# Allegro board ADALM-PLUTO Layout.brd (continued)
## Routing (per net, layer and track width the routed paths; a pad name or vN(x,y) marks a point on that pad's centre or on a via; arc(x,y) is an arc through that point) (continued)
IO_L04_34_RX_D7: length 49.7
  TOP w0.102: U5.J9 v2(27.54,30.48) ; v2(53.13,28.15) U4.J14
  L5_SIG w0.114: v2(27.54,30.48) 27.54,29.97 28.17,29.34 28.17,25.47 28.55,25.09 28.85,25.09 28.99,25.24 28.99,26.22 29.14,26.36 29.34,26.36 29.45,26.26 29.45,25.27 29.66,25.05 31,25.05 31.6,25.65 31.6,26.22 31.75,26.36 31.95,26.36 32.1,26.22 32.1,25.75 32.24,25.6 32.45,25.6 32.59,25.75 32.59,26.22 32.74,26.36 32.94,26.36 33.09,26.22 33.09,25.75 33.23,25.6 33.44,25.6 33.58,25.75 33.58,26.22 33.73,26.36 33.93,26.36 34.08,26.22 34.08,25.75 34.22,25.6 34.43,25.6 34.57,25.75 34.57,26.22 34.72,26.36 34.92,26.36 35.07,26.22 35.07,25.75 35.21,25.6 35.42,25.6 35.56,25.75 35.56,26.22 35.71,26.36 35.91,26.36 36.06,26.22 36.06,25.75 36.2,25.6 37.99,25.6 38.13,25.46 38.13,25.11 38.28,24.97 38.48,24.97 38.63,25.11 38.63,25.46 38.77,25.6 39.72,25.6 40.39,24.93 40.54,24.93 40.76,24.71 40.76,24.57 41.81,23.51 41.81,23.31 41.38,22.88 41.38,22.67 41.53,22.53 41.73,22.53 42.16,22.96 42.37,22.96 42.51,22.81 42.51,22.61 42.21,22.3 42.21,22.1 42.36,21.95 42.56,21.95 42.86,22.26 43.07,22.26 43.41,21.92 50.52,21.92 52.73,24.13 52.73,27.75 v2(53.13,28.15)
IO_L05_34_RX_D8: length 49
  TOP w0.102: U5.K7 v2(26.74,31.28) ; v2(53.13,27.35) U4.J15
  L5_SIG w0.114: v2(53.13,27.35) 53.13,23.89 50.77,21.54 41.88,21.54 41.75,21.67 40.98,21.67 40.87,21.79 40.87,22.43 40.74,22.55 40.74,22.78 41.26,23.3 41.26,23.51 41.11,23.65 40.91,23.65 40.44,23.18 40.24,23.18 40.09,23.33 40.09,23.53 40.36,23.8 40.36,23.98 40.2,24.14 39.99,24.14 39.74,23.88 39.54,23.88 39.39,24.03 39.39,24.12 39.85,24.58 39.85,24.84 39.6,25.09 39.39,25.09 38.56,24.25 38.25,24.25 37.75,24.76 37.75,25.07 37.6,25.22 37.4,25.22 37.31,25.13 37.31,24.79 37.06,24.53 36.5,24.53 36.35,24.68 36.35,24.98 36.21,25.13 36.02,25.13 35.91,25.02 35.91,24.71 35.81,24.61 35.61,24.61 35.53,24.69 35.53,25.09 35.41,25.22 35.02,25.22 34.9,25.09 34.9,24.56 34.77,24.43 34.26,24.43 34.14,24.56 34.14,25.09 34.01,25.22 33.63,25.22 33.5,25.09 33.5,24.69 33.32,24.51 32.97,24.51 32.82,24.66 32.82,25.14 32.72,25.24 32.42,25.24 32.32,25.14 32.32,24.67 32.23,24.58 30.2,24.58 30.07,24.71 29.46,24.71 29.31,24.56 28.57,24.56 27.92,25.22 27.92,29.03 27.91,29.04 27.91,29.17 27.14,29.94 27.14,30.88 v2(26.74,31.28)
IO_L05_34_RX_D9: length 49.1
  TOP w0.102: U5.J8 v2(27.54,31.28) ; v2(52.33,27.35) U4.K15
  L5_SIG w0.114: v2(27.54,31.28) 27.95,30.88 27.95,30.07 28.45,29.57 28.45,26.97 28.67,26.74 29.82,26.74 30.07,27 30.33,27 30.59,26.73 30.59,25.62 30.74,25.47 30.94,25.47 31.09,25.62 31.09,26.6 31.23,26.74 35.11,26.74 35.25,26.89 35.25,28.7 35.4,28.85 35.6,28.85 35.75,28.7 35.75,26.89 35.89,26.74 36.3,26.74 36.45,26.6 36.45,26.13 36.59,25.98 36.8,25.98 36.94,26.13 36.94,26.5 37.09,26.64 37.29,26.64 37.44,26.5 37.44,26.13 37.58,25.98 37.79,25.98 38,26.19 38,27.45 38.15,27.61 38.38,27.61 38.48,27.51 38.48,26.11 38.61,25.98 38.86,25.98 38.99,26.11 38.99,27.51 39.09,27.61 39.35,27.61 39.47,27.49 39.47,26.16 39.64,25.98 39.98,25.98 42.81,23.15 42.81,22.93 43.02,22.71 43.25,22.71 43.66,22.3 50.26,22.3 52.33,24.36 v2(52.33,27.35)
IO_L06_34_RX_D10: length 49.5
  TOP w0.102: U5.J7 v2(28.35,31.28) ; U4.H11 v2(54.73,30.55)
  L5_SIG w0.114: v2(28.35,31.28) 28.35,30.02 28.75,29.62 28.75,28.59 29.66,27.68 34.14,27.68 34.35,27.88 34.35,28.48 35.15,29.28 35.99,29.28 36.13,29.13 36.13,27.27 36.28,27.12 36.48,27.12 36.63,27.27 36.63,29.13 36.77,29.28 36.98,29.28 37.12,29.13 37.12,28.16 37.27,28.01 37.47,28.01 37.62,28.16 37.62,29.13 37.76,29.28 37.97,29.28 38.11,29.13 38.11,28.16 38.26,28.01 38.46,28.01 38.61,28.16 38.61,29.13 38.76,29.28 38.97,29.28 39.09,29.16 39.09,28.39 39.85,27.63 39.85,26.66 41.64,24.88 41.64,24.73 42.91,23.46 43.33,23.46 43.55,23.24 43.55,22.97 43.84,22.68 49.88,22.68 51.53,24.33 51.53,28.05 52.03,28.55 53.33,28.55 53.53,28.75 53.53,29.16 53.81,29.44 53.81,29.63 v2(54.73,30.55)
IO_L06_34_RX_D11: length 51.9
  TOP w0.102: U4.J11 v2(53.13,30.55) ; U5.H8 v2(29.15,31.28)
  L5_SIG w0.114: v2(53.13,30.55) 53.45,30.55 53.57,30.43 53.57,29.54 53.38,29.35 52.03,29.35 51.83,29.15 51.83,28.85 51.15,28.17 51.15,24.58 50.14,23.57 49.1,23.57 48.96,23.42 48.96,23.21 48.81,23.06 48.61,23.06 48.46,23.21 48.46,23.42 48.32,23.57 48.11,23.57 47.97,23.42 47.97,23.21 47.82,23.06 47.61,23.06 47.47,23.21 47.47,23.42 47.32,23.57 46.6,23.57 46.46,23.42 46.46,23.21 46.31,23.06 46.11,23.06 45.96,23.21 45.96,23.42 45.82,23.57 45.35,23.57 45.21,23.71 45.21,24.06 45.06,24.2 44.86,24.2 44.71,24.06 44.71,23.71 44.57,23.57 43.72,23.57 43.16,24.12 43.16,24.35 43.36,24.55 43.36,24.76 43.22,24.9 43.01,24.9 42.77,24.66 42.57,24.66 42.42,24.81 42.42,25.01 42.66,25.25 42.66,25.46 42.52,25.6 42.31,25.6 42.05,25.34 41.76,25.34 41.66,25.44 41.66,25.65 41.96,25.95 41.96,26.16 41.82,26.3 41.61,26.3 41.31,26 41.1,26 40.96,26.14 40.96,26.35 41.26,26.65 41.26,26.86 41.12,27 40.91,27 40.61,26.7 40.4,26.7 40.23,26.87 40.23,27.79 39.45,28.58 39.45,29.43 39.22,29.66 38.2,29.66 38.07,29.79 38.07,30.3 37.9,30.48 37.64,30.48 37.5,30.33 37.5,29.81 37.35,29.66 37.15,29.66 37,29.81 37,29.97 36.68,30.3 36.29,30.3 35.79,29.79 35.42,29.79 35.13,30.08 34.55,30.08 34.35,29.88 34.35,29.48 34.15,29.28 33.74,29.28 33.54,29.48 33.54,29.88 33.35,30.08 32.94,30.08 32.74,29.88 32.74,28.68 32.54,28.48 32.14,28.48 31.94,28.68 31.94,29.88 31.74,30.08 31.35,30.08 31.15,29.88 31.15,28.68 30.95,28.48 29.74,28.48 29.56,28.65 29.56,30.86 v2(29.15,31.28)
IO_L07_34_RX_FRAME: length 53.7
  TOP w0.102: v2(49.93,28.95) U4.N13 ; U5.G8 v2(29.95,31.28)
  L5_SIG w0.114: v2(29.95,31.28) 30.35,31.68 31.31,31.68 31.45,31.82 31.45,32.23 31.6,32.38 31.8,32.38 31.95,32.23 31.95,31.82 32.09,31.68 32.3,31.68 32.44,31.82 32.44,32.23 32.59,32.38 32.79,32.38 32.94,32.23 32.94,31.82 33.08,31.68 33.29,31.68 33.43,31.82 33.43,32.23 33.58,32.38 33.78,32.38 33.93,32.23 33.93,31.82 34.07,31.68 34.28,31.68 34.55,31.95 34.79,31.95 35.06,31.68 35.25,31.68 35.45,31.88 35.45,32.15 35.59,32.3 36.2,32.3 36.35,32.44 36.35,32.65 36.2,32.79 35.59,32.79 35.45,32.94 35.45,33.18 35.64,33.37 36.66,33.37 36.81,33.23 36.81,32.35 36.95,32.2 37.16,32.2 37.3,32.35 37.3,33.68 37.45,33.82 37.65,33.82 37.8,33.68 37.8,33.51 37.94,33.36 38.25,33.36 38.29,33.41 38.29,33.68 38.44,33.82 38.64,33.82 38.79,33.68 38.79,32.35 38.93,32.2 39.14,32.2 39.28,32.35 39.28,33.28 39.43,33.42 40.34,33.42 40.49,33.28 40.49,33.07 40.34,32.93 39.92,32.93 39.78,32.78 39.78,32.57 39.92,32.43 40.84,32.43 40.99,32.28 40.99,32.08 40.84,31.93 39.92,31.93 39.78,31.79 39.78,31.51 40.28,31.02 40.48,31.02 40.9,31.43 41.1,31.43 41.25,31.29 41.25,31.08 40.83,30.67 40.83,30.46 40.98,30.32 41.18,30.32 41.6,30.73 41.8,30.73 42.25,30.29 42.42,30.29 42.64,30.07 42.64,29.9 43.41,29.13 43.41,27.14 43.7,26.85 43.95,26.85 44.56,27.46 44.77,27.46 44.91,27.31 44.91,27.11 44.21,26.4 44.21,26.2 44.35,26.05 44.56,26.05 44.86,26.36 45.07,26.36 45.21,26.21 45.21,26.01 44.91,25.7 44.91,25.5 45.05,25.35 45.26,25.35 45.56,25.66 45.77,25.66 45.91,25.51 45.91,25.31 45.61,25 45.61,24.8 46.13,24.27 49.86,24.27 50.36,24.77 50.36,25.47 49.93,25.9 v2(49.93,28.95)
IO_L08_34_CTRL_OUT0: length 30.4
  TOP w0.102: v2(47.13,26.05) 48.09,25.08 49.97,25.08 51.93,27.04 U4.L15 ; U5.D4 v2(32.34,34.48)
  L5_SIG w0.114: v2(32.34,34.48) 32.75,34.88 32.75,36.28 32.95,36.48 35.07,36.48 35.91,35.63 40.99,35.63 42.52,34.11 42.52,32.45 45.95,29.02 45.95,28.52 46.23,28.25 46.83,28.25 47.13,27.94 v2(47.13,26.05)
IO_L08_34_CTRL_OUT1: length 31.1
  TOP w0.102: U5.E4 v2(31.54,34.48) ; U4.M15 51.13,27.04 49.76,25.67 49.1,25.67 v2(48.73,26.05)
  L5_SIG w0.114: v2(48.73,26.05) 48.73,28.55 48.23,29.05 46.83,29.05 45.73,30.15 45.33,30.15 43.62,31.85 43.62,32.75 42.9,33.47 42.9,34.24 41.12,36.01 36.42,36.01 35.15,37.28 32.15,37.28 31.95,37.08 31.95,34.88 v2(31.54,34.48)
IO_L09_34_TX_FRAME: length 28.7
  TOP w0.102: v2(29.94,30.48) U5.G9 ; v2(52.33,28.15) U4.L14
  L6_SIG w0.114: v2(52.33,28.15) 49.86,25.67 48.76,25.22 42.68,25.22 42.4,25.34 37.21,25.34 36.95,25.59 36.6,25.59 36.36,25.35 32.1,25.35 30.33,27.12 30.33,30.05 29.94,30.43 v2(29.94,30.48)
IO_L10_34_EN_AGC: length 35.1
  TOP w0.102: U4.L13 51.46,28.88 51.46,26.97 49.86,25.37 48.6,25.37 v2(47.93,26.05) ; U5.G5 v2(29.14,33.68)
  L5_SIG w0.114: v2(29.14,33.68) 29.55,33.28 29.55,32.68 29.75,32.48 30.55,32.48 32.15,34.08 33.45,34.08 33.65,34.28 33.65,34.89 34.01,35.25 40.87,35.25 42.14,33.98 42.14,32.33 45.13,29.35 45.13,28.35 46.63,26.84 46.63,25.84 46.9,25.57 47.45,25.57 v2(47.93,26.05)
IO_L11_34_ENABLE: length 30.6
  TOP w0.102: U4.K12 v2(52.33,29.75) ; U5.G6 v2(29.14,32.88)
  L6_SIG w0.114: v2(29.14,32.88) 29.55,33.28 29.55,33.88 29.75,34.08 30.15,34.08 31.17,35.1 31.17,35.43 31.39,35.65 32.5,35.65 32.64,35.51 43.53,35.51 45.49,33.55 46.63,33.55 47.23,32.95 47.63,32.95 47.83,33.15 47.83,33.55 48.12,33.85 48.83,33.85 49.33,33.35 50.13,33.35 51.13,32.35 51.13,30.35 51.33,30.15 51.93,30.15 v2(52.33,29.75)
IO_L11_34_TXNRX: length 32.7
  TOP w0.102: U5.H4 v2(28.35,34.48) ; U4.K11 v2(52.33,30.55)
  L6_SIG w0.114: v2(52.33,30.55) 51.93,30.95 51.93,33.95 51.73,34.15 45.93,34.15 42.16,37.92 29.48,37.92 28.75,37.18 28.75,34.88 v2(28.35,34.48)
IO_L12_MRCC_34_DATA_CLK: length 52.3
  TOP w0.102: U5.G11 v2(29.95,28.88) ; U4.L12 v2(51.53,29.75)
  L5_SIG w0.114: v2(51.53,29.75) 51.53,29.05 50.77,28.29 50.77,24.69 50.03,23.95 45.95,23.95 44.55,25.35 44.34,25.35 43.91,24.92 43.71,24.92 43.56,25.06 43.56,25.27 43.99,25.7 43.99,25.9 43.58,26.32 42.31,26.32 42.16,26.47 42.16,26.67 42.72,27.23 42.72,27.43 42.59,27.56 42.35,27.56 41.81,27.02 41.61,27.02 41.46,27.17 41.46,27.37 42.4,28.31 42.4,28.51 42.25,28.66 42.05,28.66 40.98,27.59 40.78,27.59 40.63,27.74 40.63,27.94 42.08,29.39 42.08,29.58 41.89,29.76 41.89,29.78 41.89,29.78 41.68,29.78 40.32,28.42 40.11,28.42 39.97,28.56 39.97,28.77 40.74,29.54 40.74,29.92 40.5,30.16 40.29,30.16 39.93,29.79 39.72,29.79 39.58,29.94 39.58,30.14 39.94,30.51 39.94,30.72 39.8,30.86 39.59,30.86 38.97,30.24 38.77,30.24 38.62,30.39 38.62,30.59 39.24,31.21 39.24,31.54 38.96,31.82 38.45,31.82 38.31,31.68 38.31,31.02 38.16,30.88 37.92,30.88 37.78,31.02 37.78,31.68 37.63,31.82 37.43,31.82 37.28,31.68 37.28,31.36 37.12,31.21 36.94,31.21 36.79,31.36 36.79,31.68 36.64,31.82 36.43,31.82 36.29,31.68 36.29,30.9 36.14,30.75 35.94,30.75 35.79,30.9 35.79,31.17 35.65,31.32 35.44,31.32 35.3,31.17 35.3,31.08 35.1,30.88 30.55,30.88 30.35,30.68 30.35,29.28 v2(29.95,28.88)
IO_L13_34_CTRL_OUT2: length 29.4
  TOP w0.102: U4.N11 v2(49.93,30.55) ; U5.E5 v2(30.74,33.68)
  L5_SIG w0.114: v2(30.74,33.68) 30.74,34.68 30.25,35.18 30.25,36.28 30.44,36.48 30.94,36.48 31.21,36.75 31.21,37.28 31.98,38.05 35.41,38.05 36.71,36.75 38.39,36.75 38.41,36.73 38.76,36.73 38.77,36.75 41.41,36.75 43.53,34.62 43.53,33.94 44.22,33.25 44.52,33.25 44.93,32.85 44.93,32.25 46.13,31.05 46.13,30.75 47.13,29.74 47.83,29.74 48.63,30.55 v2(49.93,30.55)
IO_L13_34_CTRL_OUT3: length 30.4
  TOP w0.102: U4.N12 v2(49.93,29.75) ; U5.E6 v2(31.54,32.88)
  L5_SIG w0.114: v2(31.54,32.88) 31.94,33.28 33.55,33.28 34.05,33.78 34.05,34.53 34.39,34.87 39.66,34.87 41.37,33.16 41.37,32.1 41.82,31.65 42.32,31.65 43.55,30.42 43.56,30.42 43.78,30.2 43.78,30.18 44.83,29.14 44.83,28.1 46.23,26.7 46.23,25.74 46.78,25.19 48.58,25.19 49.13,25.74 49.13,28.95 v2(49.93,29.75)
IO_L15_34_TX_D0: length 23.5
  TOP w0.102: v2(45.31,26.87) 45.51,27.07 49.15,27.07 49.53,27.45 U4.P15 ; v2(31.53,27.27) 31.22,27.58 31.22,27.6 U5.E12
  L6_SIG w0.114: v2(31.53,27.27) 31.53,26.89 32.57,25.85 34.9,25.85 35.28,26.24 36.55,26.24 36.7,26.08 37.28,26.08 37.43,26.24 37.88,26.24 38.14,25.98 38.52,25.98 38.77,26.24 39.22,26.24 39.48,25.98 39.85,25.98 40.11,26.24 40.56,26.24 40.82,25.98 41.19,25.98 41.44,26.24 41.89,26.24 42.15,25.98 42.52,25.98 42.78,26.24 43.23,26.24 43.24,26.23 43.31,26.23 43.55,25.98 45.82,25.98 46.2,26.36 46.2,26.62 45.95,26.87 v2(45.31,26.87)
IO_L15_34_TX_D1: length 23.3
  TOP w0.102: U5.D11 v2(32.35,28.08) ; U4.R13 48.72,29.34 48.43,29.34 48.23,29.14 45.92,29.14 v2(45.53,28.75)
  L6_SIG w0.114: v2(45.53,28.75) 44.83,28.75 44.43,28.35 44.43,27.64 44.05,27.26 43.63,27.26 43.39,27.51 41.96,27.51 41.83,27.64 41.83,28.12 41.68,28.27 41.47,28.27 41.33,28.12 41.33,27.52 41.18,27.38 40.98,27.38 40.83,27.52 40.83,28.12 40.69,28.27 40.48,28.27 40.34,28.12 40.34,27.52 40.19,27.38 39.99,27.38 39.84,27.52 39.84,28.12 39.7,28.27 39.49,28.27 39.35,28.12 39.35,27.52 39.2,27.38 38.45,27.38 37.69,28.14 35.41,28.14 34.94,27.68 32.95,27.68 32.74,27.88 32.74,28 32.67,28.08 v2(32.35,28.08)
IO_L16_34_TX_D2: length 22.6
  TOP w0.102: U5.E11 31.53,28.09 31.53,28.08 v2(31.54,28.07) ; v2(46.43,27.75) U4.R15
  L6_SIG w0.114: v2(46.43,27.75) 47.09,27.75 47.27,27.57 47.27,27.39 47.07,27.19 46.18,27.19 45.74,27.63 45.44,27.63 44.3,26.49 43.01,26.49 42.88,26.62 36.59,26.62 36.39,26.82 36.39,27.13 36.24,27.28 36.04,27.28 35.89,27.13 35.89,26.72 35.66,26.49 32.43,26.49 31.94,26.98 31.94,27.48 31.74,27.68 31.64,27.68 31.54,27.78 v2(31.54,28.07)
IO_L16_34_TX_D3: length 23.8
  TOP w0.102: U5.D10 v2(32.34,28.88) ; v2(43.79,28.27) 43.67,28.38 43.48,28.57 43.48,29.41 43.82,29.75 47.73,29.75 48.53,30.54 49.12,30.54 U4.P11
  L6_SIG w0.114: v2(43.79,28.27) 42.77,29.28 41.49,29.28 41.26,29.05 41.05,29.05 40.91,29.19 40.91,29.43 40.76,29.58 40.56,29.58 40.41,29.43 40.41,29.19 40.27,29.05 40.06,29.05 39.92,29.19 39.92,29.43 39.77,29.58 39.57,29.58 39.42,29.43 39.42,29.19 39.28,29.05 39.07,29.05 38.93,29.19 38.93,29.43 38.78,29.58 38.58,29.58 38.43,29.43 38.43,29.07 38.29,28.92 38.08,28.92 37.94,29.07 37.94,29.43 37.79,29.58 37.55,29.58 36.95,28.98 35.95,28.98 35.66,29.27 32.73,29.27 v2(32.34,28.88)
IO_L17_34_TX_D4: length 23.4
  TOP w0.102: U5.E10 v2(31.54,28.88) ; v2(47.53,30.15) 48.33,30.95 U4.R11
  L6_SIG w0.114: v2(31.54,28.88) 31.54,28.55 31.62,28.48 31.74,28.48 31.94,28.28 31.94,27.88 32.15,27.68 32.55,27.68 32.74,27.48 32.74,26.98 32.95,26.78 35.19,26.78 35.41,27 35.41,27.34 35.7,27.63 37.69,27.63 38.33,27 42.75,27 43,27.24 43.31,27.24 43.55,27 44.3,27 44.85,27.56 44.85,28.06 45.07,28.28 46.96,28.28 47.96,29.28 47.96,29.72 v2(47.53,30.15)
IO_L17_34_TX_D5: length 22.6
  TOP w0.102: U5.D9 v2(32.34,29.68) ; U4.R12 48.15,29.57 48.13,29.57 48,29.45 44.81,29.45 44.19,28.82 43.89,28.82 v2(43.89,28.82)
  L6_SIG w0.114: v2(43.89,28.82) 43.97,28.9 44.48,28.9 45.31,29.74 45.31,30.06 44.93,30.45 44.08,30.45 43.93,30.3 43.93,30.06 43.53,29.66 42.54,29.66 42.42,29.55 42.11,29.55 41.99,29.66 41.37,29.66 41.06,29.98 37.35,29.98 36.75,29.38 36.05,29.38 35.55,29.88 35.33,29.88 35.13,30.08 32.75,30.08 v2(32.34,29.68)
IO_L18_34_TX_D6: length 22.8
  TOP w0.102: U5.E9 v2(31.54,29.68) ; v2(43.79,27.63) 43.91,27.76 44.01,27.76 44.4,27.37 48.95,27.37 49.13,27.55 49.13,28.14 U4.P14
  L6_SIG w0.114: v2(31.54,29.68) 31.94,29.28 31.94,28.72 32.19,28.48 34.31,28.48 34.46,28.62 34.46,28.73 34.6,28.88 34.85,28.88 35.2,28.52 38.21,28.52 38.35,28.38 38.35,27.95 38.48,27.83 38.75,27.83 38.87,27.95 38.87,28.43 39.09,28.65 41.5,28.65 41.73,28.88 42.05,28.88 42.16,28.77 42.16,28.45 42.29,28.32 43.1,28.32 v2(43.79,27.63)
IO_L18_34_TX_D7: length 22.8
  TOP w0.102: v2(46.42,28.75) 46.63,28.75 46.63,28.75 48.23,28.75 48.42,28.94 49.12,28.94 U4.P13 ; U5.D8 v2(32.34,30.48)
  L6_SIG w0.114: v2(46.42,28.75) 46.92,28.75 47.13,28.95 47.13,30.25 46.93,30.45 46.6,30.45 46.33,30.17 45.76,30.17 45.05,30.88 42.72,30.88 42.58,30.74 42.58,30.52 42.43,30.38 42.23,30.38 42.08,30.52 42.08,30.74 41.94,30.88 41.6,30.88 41.46,30.74 41.46,30.52 41.31,30.38 37.39,30.38 37.18,30.17 36.23,30.17 35.68,30.72 35.3,30.72 35.15,30.88 32.75,30.88 v2(32.34,30.48)
IO_L19_34_TX_D8: length 22.8
  TOP w0.102: v2(47.42,31.75) 47.82,32.15 49.93,32.15 U4.N9 ; U5.E8 v2(31.54,30.48)
  L6_SIG w0.114: v2(31.54,30.48) 31.94,30.88 31.94,31.47 32.45,31.98 35.75,31.98 35.96,31.76 35.96,31.32 36.11,31.18 36.31,31.18 36.46,31.32 36.46,31.63 36.65,31.82 38.71,31.82 38.85,31.68 40.08,31.68 40.22,31.82 40.22,32.24 40.37,32.38 40.57,32.38 40.72,32.24 40.72,31.82 40.86,31.68 44.86,31.68 44.93,31.75 v2(47.42,31.75)
IO_L19_34_TX_D9: length 23.7
  TOP w0.102: U5.D7 v2(32.34,31.28) ; U4.M9 50.73,32.95 v2(49.93,32.95)
  L6_SIG w0.114: v2(32.34,31.28) 32.35,31.28 32.75,31.68 34.95,31.68 35.66,30.96 35.78,30.96 35.97,30.78 36.56,30.78 36.88,31.1 37.23,31.1 37.56,30.78 37.77,30.78 37.92,30.92 37.92,31.13 38.06,31.28 38.27,31.28 38.41,31.13 38.41,30.92 38.56,30.78 38.76,30.78 38.91,30.92 38.91,31.13 39.05,31.28 39.26,31.28 39.4,31.13 39.4,30.92 39.55,30.78 39.75,30.78 39.9,30.92 39.9,31.13 40.04,31.28 40.25,31.28 40.39,31.13 40.39,30.92 40.54,30.78 40.85,30.78 41.35,31.28 45.36,31.28 45.43,31.36 47.63,31.36 47.83,31.55 47.83,31.95 48.03,32.15 49.53,32.15 49.93,32.55 v2(49.93,32.95)
IO_L20_34_TX_D10: length 22.4
  TOP w0.102: U5.F8 v2(30.74,30.48) ; U4.R8 48.23,33.35 v2(48.22,33.34)
  L6_SIG w0.114: v2(30.74,30.48) 30.75,30.48 31.14,30.88 31.14,31.68 31.48,32.02 31.68,32.02 32.14,32.48 33.39,32.48 33.94,33.03 33.94,33.48 34.17,33.71 35.56,33.71 35.9,33.36 38.25,33.36 38.4,33.22 44.85,33.22 45.06,33.02 45.06,32.46 45.37,32.15 47.62,32.15 47.83,32.35 47.83,32.75 48.13,33.05 v2(48.22,33.34)
IO_L20_34_TX_D11: length 22.7
  TOP w0.102: U5.E7 v2(31.54,31.28) ; U4.R7 48.32,34.15 48.23,34.05 46.03,34.05 v2(44.53,32.55)
  L6_SIG w0.114: v2(44.53,32.55) 44.53,32.21 44.4,32.08 41.36,32.08 41.2,32.24 41.2,32.66 41.05,32.81 39.98,32.81 39.84,32.66 39.84,32.26 39.69,32.11 39.49,32.11 39.34,32.26 39.34,32.54 39.2,32.68 38.99,32.68 38.85,32.54 38.85,32.38 38.7,32.24 38.5,32.24 38.35,32.38 38.35,32.54 38.3,32.59 37.91,32.59 37.86,32.54 37.86,32.38 37.71,32.24 37.51,32.24 37.36,32.38 37.36,32.54 37.22,32.68 37.01,32.68 36.87,32.54 36.87,32.38 36.72,32.24 36.14,32.24 35.52,32.85 34.4,32.85 33.79,32.24 32.31,32.24 31.85,31.78 31.65,31.78 31.54,31.68 v2(31.54,31.28)
IO_L21_34_CTRL_OUT4: length 32.1
  TOP w0.102: U5.F6 v2(29.95,32.88) ; U4.M10 v2(50.73,31.35)
  L5_SIG w0.114: v2(50.73,31.35) 51.13,30.95 51.13,30.34 50.93,30.14 48.93,30.14 48.26,29.47 46.91,29.47 45.93,30.45 45.53,30.45 44.02,31.95 44.02,32.85 43.26,33.61 43.26,34.38 41.27,36.38 36.57,36.38 35.28,37.67 32.1,37.67 31.6,37.16 31.6,36.73 31.14,36.28 31.14,33.47 30.95,33.28 30.35,33.28 v2(29.95,32.88)
IO_L21_34_CTRL_OUT5: length 30.6
  TOP w0.102: U5.F5 v2(29.95,33.67) ; U4.M11 v2(50.73,30.55)
  L5_SIG w0.114: v2(29.95,33.67) 30.34,34.07 30.34,34.68 29.95,35.08 29.95,36.65 31.72,38.43 40.55,38.43 45.23,33.75 45.23,32.31 45.69,31.85 46.33,31.85 47.03,31.15 47.03,30.88 47.36,30.54 47.93,30.54 48.34,30.95 50.33,30.95 v2(50.73,30.55)
IO_L22_34_CTRL_OUT6: length 32.3
  TOP w0.102: v2(49.93,34.55) U4.N7 ; U5.F4 v2(29.94,34.48)
  L5_SIG w0.114: v2(29.94,34.48) 29.54,34.08 28.85,34.08 28.74,34.18 28.74,37.1 29.18,37.54 29.69,37.54 31.34,39.19 40.79,39.19 47.03,32.95 47.03,32.38 47.26,32.14 48.43,32.14 48.76,32.48 48.76,33.38 v2(49.93,34.55)
IO_L22_34_CTRL_OUT7: length 30.1
  TOP w0.102: U5.G4 v2(29.14,34.48) ; v2(49.93,33.75) U4.N8
  L5_SIG w0.114: v2(49.93,33.75) 49.53,33.35 49.53,32.15 48.73,31.34 47.23,31.34 46.23,32.35 46.23,33.25 40.67,38.81 31.6,38.81 29.55,36.76 29.55,34.88 v2(29.14,34.48)
IO_L23_35_SPI_CLK: length 70.4
  TOP w0.102: U5.J5 v2(27.55,33.68) ; U4.E11 v2(57.13,30.55)
  L5_SIG w0.114: v2(27.55,33.68) 27.15,33.28 24.56,33.28 21.94,30.66 21.94,23.57 28.17,17.35 34.52,17.35 35.15,16.71 42.26,16.71 42.77,17.22 54.18,17.22 54.47,17.51 57.92,17.51 58.83,18.42 58.83,25.95 59.33,26.45 59.33,28.05 59.13,28.25 59.13,30.74 58.93,30.95 57.53,30.95 v2(57.13,30.55)
IO_L23_35_SPI_ENB: length 66.4
  TOP w0.102: U4.E12 v2(57.13,29.75) ; U5.K6 v2(26.74,32.88)
  L5_SIG w0.114: v2(57.13,29.75) 57.53,30.15 58.13,30.15 58.33,29.95 58.33,28.44 59.03,27.74 59.03,26.65 58.53,26.15 58.53,18.76 57.67,17.89 54.09,17.89 53.8,17.6 42.52,17.6 41.88,16.96 37.56,16.96 36.93,17.6 28.42,17.6 22.2,23.82 22.2,30.49 24.18,32.48 26.34,32.48 v2(26.74,32.88)
IO_L24_35_SPI_DI: length 64.1
  TOP w0.102: U5.J4 v2(27.54,34.48) ; U4.E13 v2(57.13,28.95)
  L5_SIG w0.114: v2(57.13,28.95) 57.23,28.64 57.93,27.94 57.93,19.32 57.26,18.65 53.58,18.65 53.42,18.49 28.55,18.49 22.83,24.2 22.83,30.27 22.99,30.43 23.2,30.43 23.42,30.21 23.63,30.21 23.77,30.35 23.77,30.56 23.55,30.78 23.55,30.99 24.23,31.68 27.24,31.68 27.94,32.38 U5.J4 v2(27.54,34.48)
IO_L24_35_SPI_DO: length 62.6
  TOP w0.102: U4.F12 v2(56.33,29.75) ; U5.L6 v2(25.94,32.08)
  L5_SIG w0.114: v2(56.33,29.75) 56.59,29.75 56.99,29.34 57.43,29.34 57.53,29.24 57.53,28.74 58.73,27.54 58.73,26.85 58.23,26.35 58.23,18.96 57.54,18.27 53.83,18.27 53.54,17.98 28.55,17.98 22.58,23.95 22.58,30.43 24.23,32.08 v2(25.94,32.08)
JTAG_TCK: length 48.8
  TOP w0.102: TCK.1 60.3,8.71 62.84,8.71 P1.4 ; U4.G9 55.53,32.95 61.44,32.95 61.55,32.84 63.54,32.84 64.05,32.33 69.83,32.33 v1(70.34,31.82)
  L5_SIG w0.114: v1(70.34,31.82) 69.71,31.19 69.71,29.24 68.74,28.27 68.74,26.54 69.71,25.57 69.71,20.03 68.82,19.14 68.82,13.42 67.16,11.76 v1(67.16,11.12)
  BOTTOM w0.102: v1(67.16,11.12) 67.16,10.49 P1.4
JTAG_TDI: length 43.7
  TOP w0.102: TDI.1 69.82,6.8 69.82,7.44 69.06,8.2 67.41,8.2 P1.8 ; U4.L7 v2(51.53,34.55)
  L5_SIG w0.114: P1.8 63.85,10.23 63.85,16.58 62.58,17.85 62.58,22.68 61.44,23.83 61.44,30.69 59.27,32.85 55.43,32.85 54.13,34.15 51.92,34.15 51.53,34.54 v2(51.53,34.55)
JTAG_TDO: length 42.9
  TOP w0.102: U4.L8 v2(51.53,33.75) ; P1.6 66.65,8.71 69.19,8.71 69.82,8.07 TDO.1
  L5_SIG w0.114: P1.6 63.35,9.47 63.35,16.46 62.2,17.6 62.2,22.43 60.68,23.95 60.68,29.04 60.23,29.49 60.23,29.97 59.93,30.27 59.93,31.75 59.14,32.55 55.33,32.55 54.53,33.35 51.92,33.35 51.53,33.74 v2(51.53,33.75)
JTAG_TMS: length 38.5
  TOP w0.102: P1.2 61.57,7.44 TMS.1 ; U4.L9 v2(51.53,32.95)
  L5_SIG w0.114: P1.2 62.84,16.33 61.82,17.35 61.82,22.17 60.3,23.7 60.3,28.84 59.92,29.22 59.92,29.93 59.53,30.31 59.53,31.35 59.13,31.75 52.73,31.75 v2(51.53,32.95)
PG_1P0V: length 2.4
  TOP w0.305: U3.16 92.57,21.55 v1(92.94,21.92)
  BOTTOM w0.305: R6.2 v1(92.94,21.92)
PG_1P3V: length 167.7
  TOP w0.127: v1(51.53,14.17) 51.3,14.41 U12.4 ; PG_1P3V.1 46.25,10.44 43.28,10.44 43.15,10.57 U7.5 ; v2(58.73,32.15) 58.33,32.55 U4.C9
  L5_SIG w0.127: PG_1P3V.1 43.03,13.66 30.58,13.66 28.8,15.44 25.12,15.44 24.36,14.68 v1(24.36,13.28) ; v1(71.49,30.85) 71.49,30.46 70.47,29.45 70.47,28.91 71.24,28.14 71.24,26.41 70.47,25.64 v1(70.47,11.16)
  L6_SIG w0.127: v1(71.49,30.85) 71.49,31.8 70.95,32.33 69.95,32.33 69.76,32.15 v2(58.73,32.15) ; v1(70.47,11.16) 69.8,10.49 63.52,10.49 59.84,14.17 v1(51.53,14.17) 51.41,14.17 47.47,10.23 PG_1P3V.1 45.31,9.09 36.8,9.09 36.42,8.71 32.74,8.71 32.36,9.09 24.1,9.09 22.58,10.62 22.58,39.83 21.94,40.46 21.94,41.48 22.58,42.11 22.58,46.43 26.01,49.86 v1(26.01,50.87)
  BOTTOM w0.127: U1.5 25.96,50.92 v1(26.01,50.87) ; U11.4 24.36,12.29 v1(24.36,13.28) ; v1(71.49,30.85) 71.49,31.44 R15.1 71.52,32.01 C47.1 72.95,32.01 R13.2
PG_1P8V: length 12
  TOP w0.203: v2(91.79,47.49) 91.79,47.44 91.8,47.44 U6.13 ; v2(92.42,40.7) 92.3,41.05 U6.29
  L5_SIG w0.305: v2(92.42,40.7) 92.42,41.08 94.21,42.87 94.21,46.3 93.57,46.94 92.3,46.94 91.79,47.44 v2(91.79,47.49)
  BOTTOM w0.305: R59.1 92.42,39.95 v2(92.42,40.7)
PG_1P35V: length 166.3
  TOP w0.127: v1(44.91,9.93) 42.25,9.93 42.22,9.95 U7.4
  TOP w0.203: v2(92.45,48.23) 92.3,48.08 U6.12
  L5_SIG w0.127: v2(92.45,48.23) 92.43,48.21 88.47,48.21 85.58,45.32 85.58,38.59 79.87,32.88 79.87,27.8 79.36,27.29 79.36,21.19 77.71,19.54 77.71,18.27 76.19,16.75 76.19,11.87 v1(76.93,11.12)
  L6_SIG w0.127: v1(76.93,11.12) 76.47,11.59 63.01,11.59 59.92,14.68 51.28,14.68 47.53,10.93 45.88,10.93 44.91,9.95 ; v1(27.15,52.52) 27.15,50.37 23.04,46.25 23.04,10.79 24.36,9.47 32.52,9.47 32.9,9.09 36.3,9.09 36.8,9.6 44.55,9.6 44.91,9.95 ; 44.91,9.95 v1(44.91,9.93)
  BOTTOM w0.127: R50.1 83.54,45.03 85.44,46.94 91.92,46.94 92.43,47.44 92.43,48.21 v2(92.45,48.23) ; U1.4 26.89,52.79 v1(27.15,52.52)
PL_GPIO0: length 50.1
  TOP w0.127: U4.K13 v2(52.33,28.95)
  L6_SIG w0.127: v2(52.33,28.95) 52.53,28.95 52.93,29.35 53.43,29.35 54.23,30.15 56.53,30.15 56.73,29.94 56.73,29.54 56.93,29.34 57.33,29.34 57.53,29.14 57.53,28.04 57.83,27.74 57.83,26.84 58.53,26.14 58.53,18.74 65.02,12.25 81.52,12.25 83.16,10.61 83.16,8.07 L10P.1
PL_GPIO1: length 55.5
  TOP w0.102: U4.M12 v2(50.73,29.75)
  L6_SIG w0.127: v2(50.73,29.75) 50.73,29.65 51.03,29.35 52.53,29.35 52.73,29.55 52.73,30.75 52.93,30.95 57.33,30.95 57.53,30.75 57.53,29.54 57.73,29.34 58.13,29.34 58.33,29.14 58.33,28.34 59.33,27.34 59.33,19.14 64.36,14.11 67.73,14.11 68.81,13.03 82.65,13.03 85.7,9.98 85.7,8.07 L12N.1
PL_GPIO2: length 52
  TOP w0.127: U4.R10 v2(48.25,31.75)
  L6_SIG w0.127: v2(48.25,31.75) 48.25,31.53 49.53,30.25 49.53,28.81 49.79,28.55 54.07,28.55 54.35,28.83 54.35,29.17 54.53,29.34 56.53,29.34 56.73,29.14 56.73,27.84 56.93,27.64 57.33,27.64 57.53,27.44 57.53,26.32 58.13,25.72 58.13,18.54 64.78,11.88 81.25,11.88 81.89,11.25 L24N.1
PL_GPIO3: length 78.1
  TOP w0.102: v2(49.53,26.85) 49.93,27.25 49.93,28.15 U4.N14
  TOP w0.305: R97.2 99.67,10.08 97.89,10.08 L7N.1
  L6_SIG w0.127: v1(57.38,11.63) 57.38,5.03 58.52,3.88 69.57,3.88 70.46,2.99 78.71,2.99 80.24,4.52 97.13,4.52 98.78,6.17 98.78,8.58 98.04,9.32 L7N.1
  BOTTOM w0.127: v2(49.53,26.85) 50.52,25.86 50.52,23.95 50.9,23.57 50.9,21.92 57.38,15.44 v1(57.38,11.63)
PL_GPIO4: length 73
  TOP w0.102: U4.M14 50.73,28.15 50.73,26.98 50.52,26.77 50.25,26.77 v2(49.53,26.05)
  TOP w0.305: L9N.1 R68.2
  L6_SIG w0.127: L9N.1 97.13,5.53 96.49,4.9 80.11,4.9 78.59,3.38 70.58,3.38 69.7,4.26 58.81,4.26 57.88,5.11 v1(57.88,10.44)
  BOTTOM w0.127: v2(49.53,26.05) 49.53,26.04 50.14,25.44 50.14,23.82 50.52,23.44 50.52,21.66 56.66,15.52 56.66,10.82 57.04,10.44 v1(57.88,10.44)
PS-SRST#: length 33.3
  TOP w0.127: v1(71.24,29.14) 70.04,29.14 69.84,28.94 64.23,28.94 63.74,29.44 R74.2 61.95,30.3 61.7,30.55 59.53,30.55 U4.B11 ; v2(75.54,44.38) U13.A4
  L5_SIG w0.127: v2(75.54,44.38) 75.54,32.24 73.44,30.14 72.24,30.14 v1(71.24,29.14)
PS_GPIO0: length 54.7
  TOP w0.102: U4.D8 v2(57.13,33.75)
  L5_SIG w0.127: v1(63.53,36.25) 62.73,35.45 60.03,35.45 59.23,34.65 58.63,34.65 58.13,34.15 57.53,34.15 v2(57.13,33.75)
  L6_SIG w0.127: MIO0.1 92.05,10.87 84.35,18.57 84.35,22.44 v1(83.95,22.84)
  BOTTOM w0.127: v1(83.95,22.84) 83.95,23.41 83.81,23.56 83.81,26.78 82.92,27.67 81.77,27.67 81.14,28.31 81.14,30.34 76.75,34.73 66.98,34.73 66.76,34.95 64.03,34.95 63.53,35.45 v1(63.53,36.25)
PS_GPIO1: length 55.8
  TOP w0.127: v1(72.34,29.14) 71.78,29.7 69.84,29.7 68.59,30.95 63.63,30.95 63.23,31.35 59.53,31.35 U4.B10
  L5_SIG w0.127: MIO10.1 90.65,5.41 81.25,5.41 80.62,6.04 80.62,8.58 79.44,9.76 76.19,9.76 72.44,13.51 72.44,26.14 73.44,27.14 73.44,28.04 v1(72.34,29.14)
PS_GPIO2: length 52.9
  TOP w0.127: U4.D6 v2(57.13,34.55)
  L5_SIG w0.127: v1(62.73,36.25) 62.23,35.75 59.73,35.75 58.93,34.95 57.53,34.95 v2(57.13,34.55)
  L6_SIG w0.127: MIO11.1 89.51,12.77 83.35,18.93 v1(83.35,22.24)
  BOTTOM w0.127: v1(83.35,22.24) 83.35,26.6 82.79,27.16 81.65,27.16 80.76,28.05 80.76,30.21 76.54,34.43 66.85,34.43 66.64,34.65 63.83,34.65 62.73,35.75 v1(62.73,36.25)
PS_GPIO3: length 51.1
  TOP w0.127: U4.B5 59.53,36.15 60.93,36.15 61.03,36.25 v1(61.73,36.25)
  L6_SIG w0.127: MIO09.1 88.24,8.07 88.24,13.41 82.15,19.5 v1(82.15,22.24)
  BOTTOM w0.127: v1(82.15,22.24) 82.15,26.03 80.38,27.8 80.38,30.08 76.31,34.15 66.74,34.15 66.54,34.35 63.63,34.35 v1(61.73,36.25)
PS_GPIO4: length 43.3
  TOP w0.127: U4.C13 v2(58.73,28.95)
  L6_SIG w0.127: MIO53.1 86.97,11.63 85.19,13.41 68.97,13.41 66.75,15.63 63.43,15.63 60.93,18.14 60.93,26.24 58.73,28.45 v2(58.73,28.95)
PS_GPIO5: length 45.8
  TOP w0.127: U4.D13 v2(57.93,28.95)
  L5_SIG w0.127: v1(83.16,11.5) 83.16,8.58 83.67,8.07 85.7,8.07 MIO49.1
  L6_SIG w0.127: v1(83.16,11.5) 82.01,12.65 68.68,12.65 67.62,13.71 64.16,13.71 58.93,18.94 58.93,27.24 57.93,28.24 v2(57.93,28.95)
PS_GPIO6: length 136.7
  TOP w0.127: v2(59.54,29.74) U4.B12
  L5_SIG w0.127: MIO48.1 86.08,11 v1(87.6,11)
  L6_SIG w0.127: MIO48.1 84.43,8.58 83.16,7.31 83.16,5.66 82.78,5.28 79.86,5.28 78.33,3.76 70.71,3.76 69.82,4.65 59.03,4.65 58.34,5.33 58.34,11.81 57.76,12.39 56.11,12.39 54.71,11 50.26,11 49.5,10.23 48.87,10.23 44.42,5.79 31.98,5.79 29.31,3.12 25.5,3.12 24.1,4.52 17.63,4.52 16.61,5.53 v1(12.04,5.53) ; v1(87.6,11) 87.6,12.39 86.21,13.79 69.19,13.79 66.95,16.03 63.63,16.03 61.33,18.34 61.33,26.34 59.13,28.54 59.13,29.34 v2(59.54,29.74)
  BOTTOM w0.127: v1(12.04,5.53) 10.82,5.53 R102.2
PS_MIO01_500_QSPI0_SS_B: length 38.3
  TOP w0.127: U4.A5 64.13,35.75 64.54,36.15 65.14,36.15 65.89,36.9 65.89,39.5 68.35,41.97 v1(68.35,42.55) ; U13.C2 v2(72.61,48.31)
  L5_SIG w0.127: v2(72.61,48.31) 72.94,48.64 72.94,50.16 72.74,50.36 72.34,50.36 72.13,50.15 72.13,48.74 71.98,48.59 71.77,48.59 71.62,48.74 71.62,50.39 71.47,50.54 71.26,50.54 71.11,50.39 71.11,48.99 70.97,48.84 70.76,48.84 70.61,48.99 70.61,50.39 70.46,50.54 70.25,50.54 70.1,50.39 70.1,48.99 69.95,48.84 69.74,48.84 69.59,48.99 69.59,50.09 69.44,50.24 69.02,50.24 68.81,50.03 68.81,43 v1(68.35,42.55)
  BOTTOM w0.127: R14.2 73.39,47.83 73.09,47.83 v2(72.61,48.31)
PS_MIO02_500_QSPI0_IO0: length 33.8
  TOP w0.127: U4.A8 61.43,33.35 61.56,33.22 63.73,33.22 63.85,33.35 69.71,33.35 70.47,32.59 73.12,32.59 v1(74.14,33.6) ; U13.D3 v2(70.61,47.31)
  L5_SIG w0.127: v2(70.61,47.31) 71.23,47.31 72.24,46.3 72.24,41.98 72.47,41.75 72.68,41.75 72.91,41.98 73.13,41.98 73.27,41.83 73.27,41.62 73.04,41.39 73.04,41.18 73.27,40.95 73.48,40.95 73.65,41.12 73.86,41.12 74.01,40.97 74.01,40.76 73.84,40.59 73.84,40.38 74.14,40.08 v1(74.14,33.6)
  BOTTOM w0.127: v2(70.61,47.31) 69.93,47.31 R120.1
PS_MIO03_500_QSPI0_IO1: length 37.5
  TOP w0.127: U4.A7 60.36,33.72 v2(61.65,33.72) ; U13.D2 v2(70.61,48.31)
  L5_SIG w0.127: v2(61.65,33.72) 61.65,34.32 61.95,34.62 63.09,34.62 64.05,35.57 64.26,35.57 64.87,34.96 65.08,34.96 65.23,35.1 65.23,35.32 64.61,35.93 64.61,36.14 64.76,36.29 64.97,36.29 65.89,35.37 66.1,35.37 66.25,35.52 66.25,35.73 65.33,36.65 65.33,36.86 65.48,37.01 65.69,37.01 66.31,36.39 66.52,36.39 66.67,36.54 66.67,36.75 66.05,37.37 66.05,37.58 66.2,37.73 66.41,37.73 67.66,36.48 67.87,36.48 68.02,36.63 68.02,36.84 66.77,38.09 66.77,38.55 67.27,39.05 68.94,39.05 69.19,39.3 69.19,41.11 69.04,41.26 68.32,41.26 68.17,41.41 68.17,41.62 68.32,41.77 69.04,41.77 69.19,41.92 69.19,46.78 69.34,46.93 69.8,46.93 69.95,47.08 69.95,47.29 69.8,47.44 69.34,47.44 69.19,47.59 69.19,47.95 69.54,48.31 v2(70.61,48.31)
  BOTTOM w0.127: v2(70.61,48.31) 69.91,48.31 R119.1
PS_MIO04_500_QSPI0_IO2: length 36
  TOP w0.127: U13.C4 v2(71.59,45.29) ; U4.C8 v2(57.93,33.75)
  L5_SIG w0.127: v2(57.93,33.75) 58.23,33.85 58.53,34.15 60.39,34.15 61.31,33.22 62.31,33.22 63.58,34.49 67.11,34.49 67.79,33.81 68,33.81 68.15,33.96 68.15,34.17 67.47,34.85 67.47,35.06 67.62,35.21 67.83,35.21 68.51,34.53 68.72,34.53 68.87,34.68 68.87,34.89 68.19,35.57 68.19,35.78 68.34,35.93 68.55,35.93 69.23,35.25 69.44,35.25 69.59,35.4 69.59,35.61 68.91,36.29 68.91,36.5 69.09,36.68 69.3,36.68 70.17,35.81 70.38,35.81 70.53,35.96 70.53,36.17 69.66,37.04 69.66,37.25 70.08,37.67 70.08,41.86 69.57,42.36 69.57,45.03 70.46,45.92 70.97,45.92 v2(71.59,45.29)
  BOTTOM w0.127: v2(71.59,45.29) 71.6,45.29 R121.1
PS_MIO05_500_QSPI0_IO3: length 73.5
  TOP w0.127: U4.A9 63.43,32.55 63.93,32.05 69.23,32.05 v1(70.34,30.93) ; JTAG_BOOT.1 66.65,2.99 65.38,4.26 P1.5 ; U13.D4 v2(70.61,45.31)
  L5_SIG w0.127: v2(70.61,45.31) 69.95,44.65 69.95,42.62 70.37,42.2 71.13,42.2 71.28,42.05 71.28,41.84 70.86,41.41 70.86,41.2 71.01,41.06 71.22,41.06 71.64,41.48 71.85,41.48 72,41.33 72,41.12 71.57,40.7 71.57,40.49 71.72,40.34 71.93,40.34 72.36,40.76 72.57,40.76 72.72,40.61 72.72,40.4 72.29,39.98 72.29,39.77 72.47,39.59 72.68,39.59 73.17,40.07 73.38,40.07 73.53,39.93 73.53,39.72 73.04,39.23 73.04,39.02 73.63,38.43 73.63,33.14 72.54,32.05 71.46,32.05 v1(70.34,30.93) 70.34,30.34 70.09,30.08 70.09,28.79 70.84,28.04 70.84,26.64 70.09,25.88 70.09,19.52 69.31,18.74 69.31,5.53 68.55,4.77 65.89,4.77 65.38,5.28 P1.5
  BOTTOM w0.127: R122.1 70.61,44.54 v2(70.61,45.31)
PS_MIO06_500_QSPI0_SCLK: length 34.6
  TOP w0.127: U4.A10 63.23,31.75 63.73,31.25 68.8,31.25 70,30.05 71.58,30.05 v1(72.38,30.85) ; U13.B2 v2(73.61,48.31)
  L5_SIG w0.127: v1(72.38,30.85) 74.65,33.12 74.65,41.22 72.74,43.13 72.74,47.44 v2(73.61,48.31)
  BOTTOM w0.127: v2(73.61,48.31) 73.61,49.08 R116.1
PS_MIO07_500_USB_RESET_B: length 22.2
  TOP w0.127: U4.A12 60.1,29.97 v2(61.04,29.97) ; U15.27 77.3,29.55 v1(76.05,30.81)
  L6_SIG w0.127: v2(61.04,29.97) 61.3,30.24 68.14,30.24 68.34,30.04 69.44,30.04 70.84,28.64 72.64,28.64 73.24,29.24 73.24,29.93 74.12,30.81 v1(76.05,30.81)
  BOTTOM w0.127: v2(61.04,29.97) 61.04,29.64 R76.2
PS_MIO28_501_USB0_D4: length 23.7
  TOP w0.102: v1(73.25,24.48) U15.7 ; v1(66.65,24.58) 66.39,24.84 66.14,24.84 64.11,26.87 61.44,26.87 60.56,27.75 U4.A15
  L6_SIG w0.114: v1(73.25,24.48) 73.74,24.97 74.14,24.97 74.27,24.84 74.27,24.33 73.25,23.31 65.5,23.31 65.25,23.57 65.25,24.46 65.5,24.71 65.76,24.71 66.01,24.46 66.01,24.08 66.14,23.95 66.52,23.95 66.65,24.08 v1(66.65,24.58)
PS_MIO29_501_USB0_DIR: length 24.9
  TOP w0.102: U4.D11 v2(57.93,30.55) ; U15.31 75.3,29.14 v1(74.27,30.17)
  L6_SIG w0.114: v2(57.93,30.55) 58.33,30.14 58.93,30.14 59.32,30.53 59.85,30.53 60.24,30.14 60.24,29.34 60.67,28.9 63.41,28.9 63.56,28.76 63.56,28.29 63.7,28.14 63.91,28.14 64.05,28.29 64.05,28.56 64.2,28.7 64.4,28.7 64.55,28.56 64.55,28.29 64.69,28.14 64.9,28.14 65.04,28.29 65.04,28.56 65.19,28.7 65.39,28.7 65.54,28.56 65.54,28.29 66.69,27.14 70.34,27.14 71.55,28.34 72.84,28.34 73.74,29.24 73.74,29.65 v1(74.27,30.17)
PS_MIO30_501_USB0_STP: length 25.2
  TOP w0.102: U4.B15 59.62,27.25 60.55,27.25 61.31,26.49 63.98,26.49 66.52,23.95 v1(67.41,23.95) ; v1(75.28,30.17) 75.66,30.17 76.3,29.53 U15.29
  L6_SIG w0.114: v1(67.41,23.95) 67.79,23.95 68.04,23.7 71.6,23.7 72.74,24.84 72.74,25.85 73.25,26.36 74.01,26.36 75.28,27.63 v1(75.28,30.17)
PS_MIO31_501_USB0_NXT: length 24
  TOP w0.102: U15.2 73.4,26.98 v1(72.87,27.51) ; U4.C12 v2(58.73,29.75)
  L6_SIG w0.114: v1(72.87,27.51) 72.36,28.01 71.72,28.01 70.45,26.74 65.03,26.74 64.88,26.89 64.88,27.49 64.74,27.63 64.53,27.63 64.39,27.49 64.39,26.89 64.24,26.74 64.04,26.74 63.89,26.89 63.89,27.49 63.75,27.63 63.54,27.63 63.4,27.49 63.4,26.89 63.25,26.74 63.05,26.74 62.9,26.89 62.9,27.49 62.76,27.63 62.55,27.63 62.41,27.49 62.41,26.89 62.26,26.74 62.06,26.74 61.91,26.89 61.91,27.49 61.77,27.63 61.04,27.63 59.93,28.75 59.93,30.05 59.73,30.24 59.43,30.24 58.93,29.75 v2(58.73,29.75)
PS_MIO32_501_USB0_D0: length 22.8
  TOP w0.102: v1(64.74,23.44) 63.22,24.97 60.55,24.97 60.3,25.22 58.39,25.22 56.73,26.88 U4.E15 ; v1(71.98,27.47) 71.98,26.71 72.21,26.48 U15.3
  L6_SIG w0.114: v1(64.74,23.44) 64.74,24.46 65.76,25.47 66.88,25.47 67.64,26.24 70.75,26.24 v1(71.98,27.47)
PS_MIO33_501_USB0_D1: length 22.1
  TOP w0.102: v1(70.14,27.84) 72,25.98 U15.4 ; U4.C11 58.74,30.54 v2(58.73,30.54)
  L6_SIG w0.114: v2(58.73,30.54) 59.13,30.74 59.33,30.94 59.94,30.94 60.54,30.34 60.54,29.64 60.94,29.24 63.74,29.24 63.94,29.04 65.75,29.04 66.95,27.84 67.26,27.84 67.41,27.98 67.41,28.76 67.55,28.9 67.76,28.9 67.9,28.76 67.9,27.98 68.05,27.84 68.25,27.84 68.4,27.98 68.4,28.76 68.54,28.9 68.75,28.9 68.89,28.76 68.89,27.98 69.04,27.84 v1(70.14,27.84)
PS_MIO34_501_USB0_D2: length 25.3
  TOP w0.102: U4.D15 57.53,26.87 58.29,26.11 60.17,26.11 60.93,25.35 63.6,25.35 65.38,23.57 v1(65.38,22.43) ; v1(73.25,25.48) U15.5
  L6_SIG w0.114: v1(65.38,22.43) 65.89,22.93 74.39,22.93 74.7,23.24 74.7,25.17 74.39,25.48 v1(73.25,25.48)
PS_MIO35_501_USB0_D3: length 23.7
  TOP w0.102: U4.A14 60.78,28.55 61.69,27.63 64.36,27.63 66.39,25.6 68.3,25.6 v1(68.81,25.09) ; v1(71.22,25.47) 71.72,24.98 U15.6
  L6_SIG w0.114: v1(68.81,25.09) 68.3,25.09 68.04,25.35 68.04,25.73 68.17,25.85 69.31,25.85 69.44,25.73 69.44,24.84 69.57,24.71 69.94,24.71 70.08,24.86 70.08,25.71 70.23,25.85 70.43,25.85 70.58,25.71 70.58,24.86 70.72,24.71 71.47,24.71 71.98,25.22 71.98,25.83 71.83,25.98 71.35,25.98 71.22,25.85 v1(71.22,25.47)
PS_MIO36_501_USB0_CLK: length 23.1
  TOP w0.102: v1(67.41,25.09) 66.77,25.09 66.65,25.22 66.27,25.22 64.23,27.25 61.57,27.25 60.68,28.14 59.54,28.14 U4.B14 ; U15.1 v1(74.1,28.14)
  L6_SIG w0.114: v1(67.41,25.09) 68.43,24.08 68.76,24.08 69.01,24.33 69.25,24.33 69.5,24.08 69.75,24.08 70,24.33 70.24,24.33 70.5,24.08 71.35,24.08 72.36,25.09 72.36,26.49 72.62,26.74 73.89,26.74 74.9,27.76 74.9,28.52 74.78,28.65 74.23,28.65 74.1,28.52 v1(74.1,28.14)
PS_MIO37_501_USB0_D5: length 24.4
  TOP w0.102: U4.C14 58.7,28.18 58.7,27.33 59.15,26.87 60.42,26.87 61.19,26.11 63.85,26.11 66.39,23.57 v1(66.39,22.43) ; U15.9 74.8,22.71 74.52,22.43 v1(74.14,22.43)
  L6_SIG w0.114: v1(74.14,22.43) 73.34,22.43 73.19,22.28 73.19,21.94 73.05,21.79 72.84,21.79 72.7,21.94 72.7,22.28 72.55,22.43 72.35,22.43 72.2,22.28 72.2,21.94 72.06,21.79 71.85,21.79 71.71,21.94 71.71,22.28 71.56,22.43 71.36,22.43 71.21,22.28 71.21,21.94 71.07,21.79 70.86,21.79 70.72,21.94 70.72,22.28 70.57,22.43 70.37,22.43 70.22,22.28 70.22,21.94 70.08,21.79 67.54,21.79 66.9,22.43 v1(66.39,22.43)
PS_MIO38_501_USB0_D6: length 25.5
  TOP w0.102: U4.A13 60.33,28.95 60.89,28.95 61.82,28.01 64.62,28.01 v1(66.52,26.11) ; v1(74.14,21.41) 75.3,22.57 U15.10
  L6_SIG w0.114: v1(66.52,26.11) 65.89,26.11 64.23,24.46 64.23,22.55 64.87,21.92 66.65,21.92 67.16,21.41 v1(74.14,21.41)
PS_MIO39_501_USB0_D7: length 25.5
  TOP w0.102: v1(66.39,21.41) 65.89,21.92 65.89,23.57 63.73,25.73 61.06,25.73 60.3,26.49 58.47,26.49 57.96,27 57.96,28.12 U4.D14 ; v1(76.58,22.3) 76.8,22.53 U15.13
  L6_SIG w0.114: v1(76.58,22.3) 75.18,20.9 66.9,20.9 v1(66.39,21.41)
PWR_CLK: length 38.2
  TOP w0.127: U3.1 91.66,22.55 v1(92.43,23.31)
  L6_SIG w0.203: v1(92.43,23.31) 92.43,25.02 91.93,25.51 91.93,29.19 92.7,29.96 92.7,39.23 92.06,39.86 89.9,39.86 88.38,41.39 80.81,41.39 v1(79.77,42.43)
  BOTTOM w0.203: R89.2 83.83,42.4 R90.1 v1(79.77,42.43)
RX1A_N: length 2.6
  TOP w0.229: U5.M2 arc(25.38,35.82) 25.18,35.87 24.99,35.87 arc(24.64,35.93) 24.33,36.09 23.84,36.45 arc(23.54,36.54) C133.2
RX1A_P: length 2.5
  TOP w0.229: U5.M1 arc(25.49,36.34) 25.35,36.28 24.99,36.28 arc(24.77,36.32) 24.57,36.42 23.87,36.93 arc(23.76,37.06) 23.71,37.23 arc(23.72,37.31) C134.2
RX2A_N: length 5.6
  TOP w0.229: C175.2 36.84,39.08 arc(36.88,39.08) 36.93,39.07 37.12,38.82 arc(37.17,38.67) 37.21,38.51 arc(37.2,38.39) 37.15,38.29 arc(37.08,38.2) 36.99,38.12 ; 36.99,38.12 36.98,38.12 arc(36.99,38.04) 37.01,37.97 37.07,37.81 arc(37.1,37.75) 37.14,37.7 arc(37.23,37.55) 37.19,37.38 arc(37,37.14) 36.78,36.92 arc(36.46,36.66) 36.11,36.43 arc(35.66,36.22) 35.18,36.1 34.99,36.07 arc(34.98,36.07) 34.96,36.07 34.71,36.07 arc(34.62,36.09) 34.55,36.14 34.41,36.27 arc(34.36,36.35) 34.34,36.43 U5.A1 ; 36.99,38.12 R69.2
RX2A_P: length 5.7
  TOP w0.229: R104.2 37.76,38.26 37.74,38.27 ; 37.74,38.27 37.74,38.47 arc(37.74,38.63) 37.74,38.79 C176.2 ; 37.74,38.27 arc(37.74,38.15) 37.73,38.03 arc(37.72,37.93) 37.7,37.84 arc(37.68,37.7) 37.65,37.56 arc(37.64,37.51) 37.63,37.46 arc(37.6,37.3) 37.52,37.15 arc(37.47,37.08) 37.42,37.01 arc(37.4,36.98) 37.38,36.96 arc(37.35,36.92) 37.33,36.89 arc(37.32,36.88) 37.31,36.87 37.28,36.83 arc(37.24,36.79) 37.2,36.74 arc(37.12,36.68) 37.05,36.62 arc(36.7,36.34) 36.33,36.09 arc(36.32,36.08) 36.32,36.08 arc(36,35.92) 35.67,35.79 arc(35.62,35.77) 35.56,35.76 arc(35.51,35.75) 35.47,35.74 arc(35.45,35.73) 35.44,35.73 arc(35.43,35.73) 35.43,35.73 arc(35.32,35.71) 35.22,35.69 35.05,35.67 arc(35.01,35.66) 34.96,35.66 34.82,35.66 arc(34.8,35.66) 34.78,35.66 arc(34.77,35.66) 34.76,35.66 34.71,35.66 arc(34.68,35.66) 34.66,35.66 arc(34.56,35.67) 34.45,35.68 U5.A2
SYNC: length 7.1
  TOP w0.305: 90.11,17.85 U3.11 U3.10 ; U3.10 U3.9 ; U3.10 89.46,17.85 ; 88.37,18.6 U3.9 ; U3.9 88.81,17.85
  TOP w1.524: 89.44,14.04 L4.1 88.45,16.14
TX1A_N: length 3.8
  TOP w0.229: U5.M8 25.42,31 arc(25.33,31.06) 25.23,31.08 25.11,31.08 arc(24.94,31.05) 24.79,30.95 24.16,30.32 arc(23.88,30.13) 23.56,30.07 23.22,30.07 arc(22.91,30.01) 22.65,29.83 L8.2
TX1A_P: length 3.8
  TOP w0.229: U5.M7 25.44,31.57 arc(25.35,31.51) 25.23,31.49 25.11,31.49 arc(24.78,31.42) 24.5,31.23 23.87,30.6 arc(23.73,30.51) 23.56,30.47 23.22,30.47 arc(22.91,30.54) 22.64,30.72 L9.2
TX2A_N: length 8
  TOP w0.229: C130.1 40.78,29.84 arc(40.66,29.85) 40.55,29.88 arc(40.47,29.92) 40.4,29.97 arc(40.31,30.04) 40.23,30.12 arc(40.19,30.17) 40.14,30.22 arc(40.09,30.27) 40.04,30.32 arc(40.03,30.33) 40.03,30.33 39.94,30.41 arc(39.91,30.44) 39.88,30.46 arc(39.7,30.71) 39.62,31 39.59,31.19 arc(39.59,31.25) 39.58,31.3 L1.2 39.33,31.4 arc(39.12,31.4) 38.92,31.46 arc(38.83,31.53) 38.75,31.61 arc(38.68,31.72) 38.59,31.82 arc(38.56,31.85) 38.53,31.89 arc(38.29,32.09) 37.98,32.18 37.98,32.17 37.85,32.18 arc(37.65,32.17) 37.45,32.12 36.51,31.75 arc(36.4,31.72) 36.29,31.69 35.75,31.63 arc(35.68,31.62) 35.61,31.62 35.19,31.66 arc(35.19,31.66) 35.18,31.66 34.96,31.67 arc(34.94,31.67) 34.91,31.67 34.71,31.68 arc(34.58,31.68) 34.46,31.68 U5.A7
TX2A_P: length 8
  TOP w0.229: 40.17,29.18 40.21,29.18 40.23,29.2 40.23,29.21 arc(40.21,29.38) 40.14,29.54 40.05,29.69 arc(40,29.75) 39.95,29.81 arc(39.86,29.93) 39.75,30.03 39.66,30.11 arc(39.44,30.25) 39.18,30.3 L7.2 38.53,30.34 38.55,30.83 arc(38.53,31.1) 38.44,31.35 arc(38.04,31.7) 37.5,31.7 36.58,31.34 arc(36.56,31.33) 36.54,31.32 arc(36.52,31.32) 36.5,31.31 35.8,31.22 arc(35.69,31.22) 35.58,31.22 34.93,31.27 arc(34.92,31.27) 34.91,31.27 34.66,31.27 arc(34.55,31.25) 34.46,31.18 arc(34.37,31.04) U5.A8
TX_VCO_1P1V_SUPPLY: length 3.4
  TOP w0.305: U5.A11 v2(34.74,28.08) ; U5.B11 v2(33.94,28.08)
  BOTTOM w0.305: v2(34.74,28.08) 35.16,28.08 C128.1 R52.1
  BOTTOM w0.406: v2(33.94,28.08) v2(34.74,28.08)
UART_RX: length 162.6
  TOP w0.127: U4.C6 v2(57.93,35.35) ; RX.1 60.93,4.26 62.08,4.26 62.84,5.03 P1.1
  L5_SIG w0.127: v1(64.87,11.11) 65.51,11.76 66.14,11.76 67.79,13.41 67.79,21.95 65.5,24.23 65.5,26.36 66.52,27.38 66.52,30.05 64.87,31.7 60.93,31.7 59.28,33.35 56.93,33.35 56.73,33.55 56.73,35.55 56.93,35.75 57.53,35.75 v2(57.93,35.35)
  L6_SIG w0.203: v1(98.52,22.93) 98.52,42.24 98.02,42.75 98.02,45.41 94.21,49.22 94.21,52.26 87.97,58.49 74.4,58.49 66.65,66.24 v1(61.69,66.24)
  BOTTOM w0.127: v1(98.52,22.93) 98.52,16.46 94.59,12.52 67.64,12.52 66.52,11.4 66.52,10.87 66.27,10.61 65.76,10.61 65.26,11.11 v1(64.87,11.11) 61.95,8.19 61.95,7.06 P1.1
  BOTTOM w0.254: v1(61.69,66.24) R95.2
UART_TX: length 153.5
  TOP w0.127: 64.11,4.9 P1.3 ; U4.B7 v2(59.53,33.75)
  TOP w0.152: TX.1 64.11,4.9
  L5_SIG w0.127: v1(66.01,11.12) 68.43,13.54 68.43,24.87 68.38,24.91 68.38,25.27 68.43,25.32 68.43,28.01 67.92,28.52 67.92,29.79 65.38,32.33 60.95,32.33 59.53,33.75 v2(59.53,33.75)
  L6_SIG w0.203: v1(65.89,65.1) 67.2,65.1 74.31,57.99 87.86,57.99 93.7,52.14 93.7,49.14 97.51,45.33 97.51,42.62 97.89,42.24 v1(97.89,22.93)
  BOTTOM w0.127: 66.01,11.5 v1(66.01,11.12) ; 66.01,11.5 67.41,12.9 94.23,12.9 97.89,16.56 v1(97.89,22.93) ; 66.01,11.5 65.76,11.76 64.62,11.76 61.57,8.71 61.57,5.66 62.08,5.15 63.85,5.15 64.11,5.41 P1.3 ; 65.81,65.03 v1(65.89,65.1)
  BOTTOM w0.254: U9.2 65.81,65.03
UNNAMED_2_ADM7160V2_I254_VIN: length 4.3
  TOP w0.305: 50.46,16.12 U12.6 51.14,15.71
  TOP w0.762: 51.83,15.4 E2.2 52.8,16.25 ; 50.96,16.65 C173.1 51.6,17.35
UNNAMED_2_ADM7160V2_I348_VIN: length 3.9
  BOTTOM w0.305: U11.6 26.18,10.98 C195.1 28.22,10.98 E7.2
UNNAMED_2_ADP1754_I93_SS: length 1.5
  BOTTOM w0.305: U1.7 24.67,53.02 C2.1
UNNAMED_2_ADP1754_I233_SS: length 1.5
  TOP w0.203: C12.1 44.67,12.21 U7.7
UNNAMED_2_ADP2164_I29_EN: length 12.6
  TOP w0.203: C13.1 89.75,24.46 92.94,24.46 93.7,23.7 93.7,20.9
  TOP w0.305: R1.1 93.44,20.61 ; R1.1 93.9,20.2 ; R1.1 92.99,20.2 ; 92.5,20.9 U3.15 U3.14 92.5,20.25 ; U3.3 89.46,24.16 C13.1
UNNAMED_2_ADP2164_I29_RT: length 1.8
  TOP w0.127: v1(90.11,23.53) U3.2
  BOTTOM w0.127: R3.2 90.88,23.53 v1(90.11,23.53)
UNNAMED_2_RES_I251_N2: length 2.3
  BOTTOM w0.305: R4.2 85.09,19.53 84.68,19.12 R7.1
UNNAMED_3_ICXC7Z010_I16_PSCLK50: length 7
  TOP w0.127: U4.C7 58.73,34.55 60.24,34.55 60.42,34.36
  TOP w0.305: R12.2 61.95,34.74 61.57,34.36 60.42,34.36
UNNAMED_3_ICXC7Z010_I16_PSMIO75: length 5
  TOP w0.127: U4.D9 v2(57.93,32.15)
  BOTTOM w0.127: v2(57.93,32.15) 58.37,32.59 59.03,32.59 59.15,32.46 61.75,32.46 R83.2
UNNAMED_3_ICXC7Z010_I16_PSMIO85: length 8.8
  TOP w0.127: R84.1 66.52,36.9 65.37,35.75 64.63,35.75 64.24,35.35 59.54,35.35 U4.B6
UNNAMED_3_RES_I2_N1: length 2.6
  TOP w0.305: Y2.1 70.32,36.14 R8.2 71.6,36.15 R9.1
UNNAMED_3_RES_I48_N1: length 2.5
  TOP w0.305: Y2.3 68.1,34.74 R12.1
UNNAMED_4_ICMT41K256M16_I98_ZQ: length 4.2
  TOP w0.127: U2.L8 52.82,49.47 v2(52.82,46.57)
  BOTTOM w0.165: R165.1 52.82,45.86 v2(52.82,46.57)
UNNAMED_4_ICTPS51206_I44_S3: length 1.5
  TOP w0.203: R222.2 42,59.92 U14.7
UNNAMED_4_ICTPS51206_I44_S5: length 2.2
  TOP w0.203: U14.9 41.2,58.94 40.89,59.26 40.63,59.26 R221.2
UNNAMED_4_ICTPS51206_I44_VLDOIN: length 2.2
  TOP w0.203: U14.2 41.2,56
  TOP w0.305: R44.2 40.74,54.63 41.2,55.1 41.2,56
UNNAMED_4_ICTPS51206_I44_VTTSNS: length 4.1
  TOP w0.203: v1(42.77,55.95) 42.52,55.95 42.4,56.07 U14.5
  BOTTOM w0.203: R43.2 41.26,55.46 41.5,55.7 42.52,55.7 v1(42.77,55.95)
  BOTTOM w0.305: C80.1 40.3,54.81 41.13,54.81 R43.2
UNNAMED_4_ICXC7Z010_I26_PSDDR_1: length 3.4
  TOP w0.127: U4.H3 v2(54.73,37.75)
  BOTTOM w0.127: v2(54.73,37.75) 54.33,38.15 54.33,39.76 R40.1
UNNAMED_4_ICXC7Z010_I26_PSDDRVR: length 1.2
  TOP w0.127: U4.J3 v2(53.13,37.75)
  BOTTOM w0.127: v2(53.13,37.75) 53.22,37.66 R41.1
UNNAMED_5_CAP_I83_N1: length 24.5
  TOP w0.305: U4.F7 56.33,34.55 v2(56.33,34.55)
  L6_SIG w0.102: 57.53,33.19 57.53,33.95 57.33,34.15 56.73,34.15 56.73,33.21 56.75,33.19 56.19,33.19 55.93,33.45 U4.F7
  L6_SIG w0.305: 56.73,34.15 v2(56.33,34.55) U4.F7 ; 62.73,33.5 62.42,33.19 56.75,33.19
  L6_SIG w0.508: 62.73,33.5 64.76,35.53 65.51,35.53 66.84,36.85 66.84,39.55 v1(67.34,40.06)
  BOTTOM w0.305: v2(56.33,34.55) 55.85,35.03 C98.1
  BOTTOM w0.508: v1(67.34,40.06) 67.34,40.82 C93.1 67.36,41.45 67,41.81 67,42.61 E5.2
UNNAMED_5_CAP_I83_N2: length 29.1
  TOP w0.305: U4.J7 v2(53.93,34.55) 53.93,34.55 U4.H7 ; U4.F8 v2(55.53,33.75) U4.G8 ; U4.F6 v2(56.33,35.35)
  L6_SIG w0.305: 54.73,34.55 54.73,34.05 55.03,33.75 v2(55.53,33.75) 55.53,33.05 55.86,32.71 63,32.71 63.34,33.05 ; 54.73,34.55 v2(53.93,34.55) ; 54.73,34.55 55.52,35.35 v2(56.33,35.35)
  L6_SIG w0.508: v1(68.34,40.06) 68.34,36.05 66.99,34.7 64.99,34.7 63.34,33.05
  BOTTOM w0.305: C98.2 56.11,35.67 56.33,35.45 v2(56.33,35.35)
  BOTTOM w0.508: E6.2 C93.2 68.34,40.83 v1(68.34,40.06)
UNNAMED_5_DIOLED_I62_N: length 2.5
  TOP w0.127: DS2.C 107.67,14.04 106.97,14.74 R87.1
UNNAMED_5_DIOLED_I91_N: length 1.6
  TOP w0.127: DS1.C 107.58,21.41 R48.1
UNNAMED_5_ICXC7Z010_I93_DONE0: length 67.5
  TOP w0.127: U4.M7 v2(50.73,34.55) ; v1(101.95,19.38) 102.39,19.81 Q1.1
  L6_SIG w0.127: v2(50.73,34.55) 51.13,34.95 52.53,34.95 52.73,34.75 52.73,32.55 53.53,31.75 68.74,31.75 70.14,30.34 72.64,30.34 74.04,31.75 77.65,31.75 82.23,27.16 83.12,27.16 85.82,24.46 85.82,18.36 86.65,17.54 90.33,17.54 92.17,19.38 v1(101.95,19.38)
UNNAMED_5_ICXC7Z010_I93_INITB0: length 8.3
  TOP w0.127: R47.1 64.42,36.85 v1(62.23,36.85) ; U4.D5 v2(57.93,36.15)
  L5_SIG w0.127: v1(62.23,36.85) 61.33,36.85 60.63,36.15 v2(57.93,36.15)
UNNAMED_5_ICXC7Z010_I93_PROGRAM: length 4
  TOP w0.127: U4.K6 v2(52.33,35.35)
  BOTTOM w0.127: v2(52.33,35.35) 52.33,35.35 51.53,35.35 51.13,34.95 51.13,33.44 R46.1
UNNAMED_5_ICXC7Z010_I93_VCCBATT: length 5.2
  TOP w0.127: U4.E6 v2(57.13,35.35)
  BOTTOM w0.127: v2(57.13,35.35) 57.53,34.94 57.53,34.35 57.73,34.15 59.74,34.15 59.93,33.95 59.93,33.05 R45.2
UNNAMED_5_ICXC7Z010_I93_VP0: length 21.7
  TOP w0.127: v2(55.53,34.55) 55.13,34.15 U4.G7
  L6_SIG w0.127: v1(66.54,40.86) 66.54,40.06 66.34,39.85 66.34,37.15 65.34,36.15 64.44,36.15 63.39,35.1 62.49,35.1 61.64,34.25 58.93,34.25 58.23,34.95 55.93,34.95 v2(55.53,34.55)
  BOTTOM w0.127: v1(66.54,40.86) 66.54,40.26 66.74,40.06 66.74,39.45 R11.2 R91.1
  BOTTOM w0.305: v1(66.54,40.86) 66.54,40.86 66.14,40.46 65.1,40.46 R66.2
UNNAMED_5_RES_I63_N2: length 2.6
  TOP w0.127: R87.2 105.55,14.59 Q4.3
UNNAMED_5_RES_I90_N2: length 2.7
  TOP w0.127: Q1.3 105.38,19.03 105.38,21.17 R48.2
UNNAMED_7_AD9363_I87_RBIAS: length 3.7
  TOP w0.178: 25.94,33.68 25.14,33.68
  TOP w0.305: U5.L4 25.94,33.68
  TOP w0.406: 25.14,33.68 24.78,33.68 arc(24.14,33.8) 23.6,34.16 R49.2
UNNAMED_7_AD9363_I87_XTALN: length 19.2
  TOP w0.102: v2(24.99,27.12) U5.M12
  BOTTOM w0.102: C204.2 14.03,14.29 arc(14.03,14.3) C157.2 14.03,15.46 arc(14.04,15.49) C124.1 14.06,15.86 arc(14.07,15.93) 14.11,15.99 14.27,16.15 arc(14.27,16.15) 14.28,16.16 24.81,26.69 arc(24.95,26.89) v2(24.99,27.12)
UNNAMED_7_CAP_I14_N1: length 9.8
  TOP w0.102: v1(9.7,10.79) 9.76,10.85 arc(10.19,11.49) R86.2
  TOP w0.127: R99.1 9.65,12.04 9.78,12.16 arc(9.88,12.22) 10,12.24 R86.2
  BOTTOM w0.102: C157.1 11.05,14.3 arc(10.55,14.2) 10.13,13.92 arc(9.81,13.44) 9.7,12.87 v1(9.7,10.79)
UNNAMED_7_CAP_I22_N2: length 1
  BOTTOM w0.305: C126.2 R51.1
UNNAMED_7_CAP_I25_N1: length 1.2
  BOTTOM w0.305: R52.2 36.15,26.2 arc(36.15,26.19) C127.1
UNNAMED_7_CAP_I57_N2: length 2.2
  TOP w0.483: T5.4 arc(19.12,31.31) C132.2
UNNAMED_7_CAP_I58_N2: length 2.2
  TOP w0.483: T5.6 arc(19.12,29.22) C131.2
UNNAMED_7_CAP_I85_N1: length 2.2
  TOP w0.483: T1.4 22.98,38.26 arc(23.15,38.01) C134.1
UNNAMED_7_CAP_I86_N1: length 2.2
  TOP w0.483: C133.1 22.68,36.76 22.18,36.76 arc(21.38,36.86) T1.6
UNNAMED_7_CAP_I92_N1: length 2.8
  TOP w0.102: C179.1 arc(21.39,11.42) D7.2 arc(21.39,10) CLK_IN.1
UNNAMED_7_CAP_I92_N2: length 2.6
  TOP w0.102: R96.1 C179.2 arc(20.83,12.64) R10.1
UNNAMED_7_CAP_I93_N1: length 4.3
  TOP w0.102: U17.4 arc(18.86,13.16) R96.2 arc(19.84,14.91) C180.1
UNNAMED_7_CAP_I116_N1: length 2
  TOP w0.483: C175.1 arc(36.71,40.03) 36.53,40.3 36.42,40.41 arc(36.08,40.92) T2.6
UNNAMED_7_CAP_I117_N1: length 2
  TOP w0.483: C176.1 37.74,40.04 arc(37.78,40.24) 37.89,40.4 38.18,40.7 arc(38.42,41.07) T2.4
UNNAMED_7_CAP_I118_N2: length 2.6
  TOP w0.483: C130.2 41.15,28.6 arc(41.17,28.36) 41.24,28.13 41.51,27.47 arc(41.6,27.17) 41.6,26.85 arc(41.59,26.79) T3.6
UNNAMED_7_CAP_I119_N2: length 2.6
  TOP w0.483: 39.05,26.45 39.05,26.54 arc(39.08,26.8) 39.17,27.05 39.35,27.41 arc(39.54,27.74) 39.77,28.05 arc(39.93,28.23) 40.12,28.39 40.36,28.58 arc(40.38,28.58) C156.2
